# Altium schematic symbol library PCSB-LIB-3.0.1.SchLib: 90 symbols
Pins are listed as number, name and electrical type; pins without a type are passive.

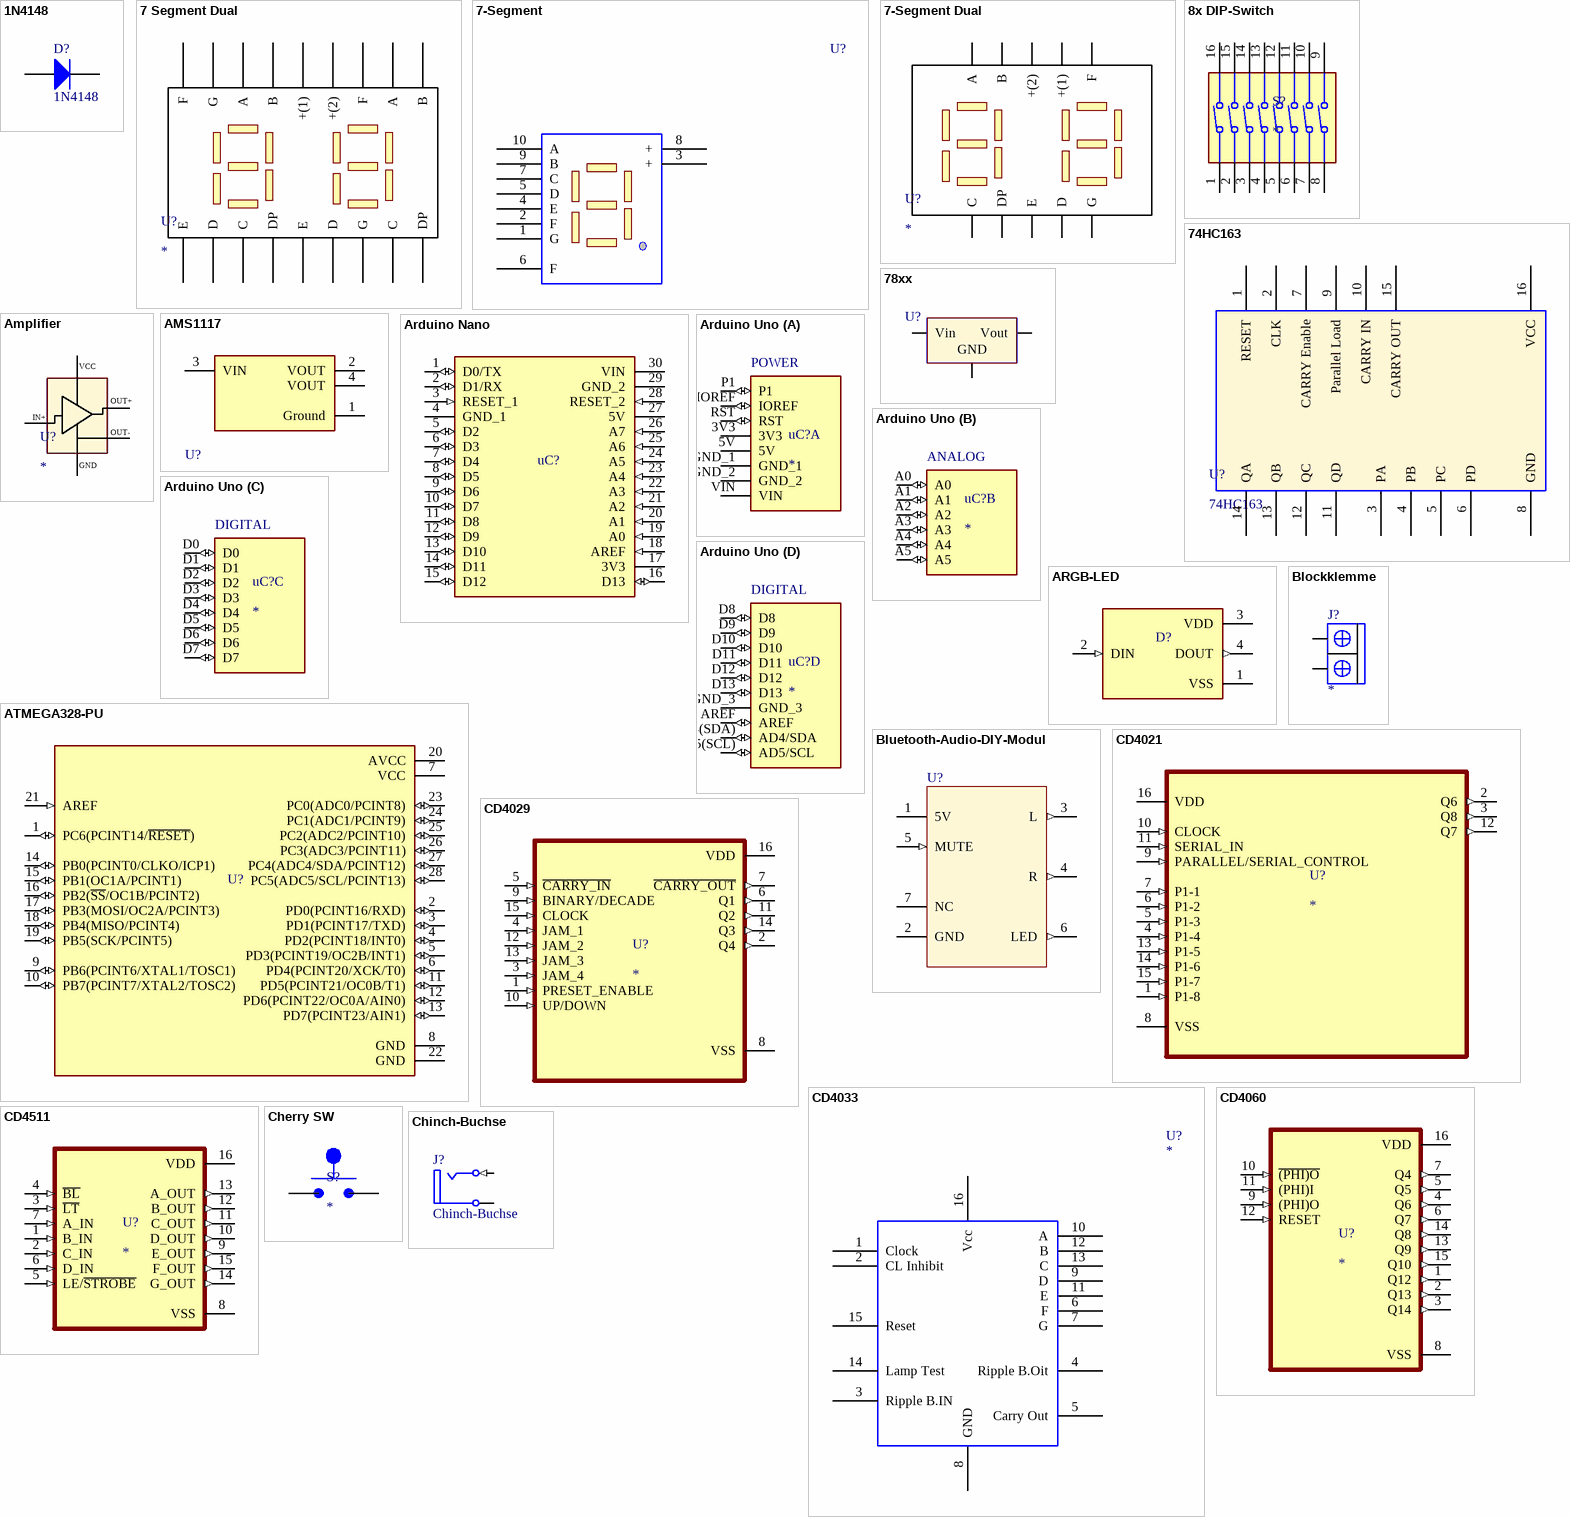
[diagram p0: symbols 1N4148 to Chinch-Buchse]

## 1N4148
designator D?
Diode
footprint DIODE-0.4
pins: 1 A, 2 K

## 7 Segment Dual
designator U?
footprint 7 Segment Dual Klein
footprint 7 Segment Dual Groß
pins: 1 E, 2 D, 3 C, 4 DP, 5 E, 6 D, 7 G, 8 C, 9 DP, 10 B, 11 A, 12 F, 13 +(2), 14 +(1), 15 B, 16 A, 17 G, 18 F

## 7-Segment
designator U?  (value not drawn)
7-Segment Display
footprint 7-Segment
pins: 1 G, 2 F, 3 +, 4 E, 5 D, 6 F, 7 C, 8 +, 9 B, 10 A

## 7-Segment Dual
designator U?
footprint 7 Seg Einfach
pins: 1 C, 2 DP, 3 E, 4 D, 5 G, 6 F, 7 +(1), 8 +(2), 9 B, 10 A

## 8x DIP-Switch
designator S?
MP: 418117170908; MF: WÃ¼rth Elektronik
footprint DIP 2x8
pins: 1, 2, 3, 4, 5, 6, 7, 8, 9, 10, 11, 12, 13, 14, 15, 16

## 74HC163
designator U?
Counter-IC; Mfr_Name: Texas Instruments
footprint DIP-16
pins: 1 RESET, 2 CLK, 3 PA, 4 PB, 5 PC, 6 PD, 7 CARRY Enable, 8 GND, 9 Parallel Load, 10 CARRY IN, 11 QD, 12 QC, 13 QB, 14 QA, 15 CARRY OUT, 16 VCC

## 78xx
designator U?  (value not drawn)
Spannungswander
footprint TO-92/BCE
footprint TO-220H
footprint TO-220V
pins: 1 Vin, 2 Vout, 3 GND

## Amplifier
designator U?
footprint Verstärker 5V
pins: 0, 1, 2, 3, 4

## AMS1117
designator U?
Spannungswandler; Manufacturer Part Number: AMS1117-3.3; Manufacturer: Advanced Monolithic Systems; Dropout Voltage: 1.1V; Output Type: Fixed; Nominal Supply Current: 5mA; Output Current: 1A; Output Voltage: 3.3V; Max Power Dissipation: 1.2W; Max Supply Voltage: 15V; Number Of Outputs: 1; Standoff Height: 0.64mm; Max Junction Temp: +125°C
footprint AMS1117_1
footprint AMS1117_2
footprint AMS1117_3
pins: 1 Ground (power), 2 VOUT, 3 VIN (power), 4 VOUT

## Arduino Nano
designator uC?  (value not drawn)
Microcontroller; MP: A000005
footprint Arduino-Nano
pins: 1 D0/TX (io), 2 D1/RX (io), 3 RESET_1 (in), 4 GND_1 (power), 5 D2 (io), 6 D3 (io), 7 D4 (io), 8 D5 (io), 9 D6 (io), 10 D7 (io), 11 D8 (io), 12 D9 (io), 13 D10 (io), 14 D11 (io), 15 D12 (io), 16 D13 (io), 17 3V3 (power), 18 AREF (in), 19 A0 (in), 20 A1 (in), 21 A2 (in), 22 A3 (in), 23 A4 (in), 24 A5 (in), 25 A6 (in), 26 A7 (in), 27 5V (power), 28 RESET_2 (in), 29 GND_2 (power), 30 VIN (power)

## Arduino Uno
designator uC?
MP: A000066; MF: Arduino
footprint Arduino Uno
part A pins: 3V3 (power), 5V (power), GND_1 (power), GND_2 (power), IOREF (io), P1 (io), RST (io), VIN (power)
part B pins: A0 (io), A1 (io), A2 (io), A3 (io), A4 (io), A5 (io)
part C pins: D0 (io), D1 (io), D2 (io), D3 (io), D4 (io), D5 (io), D6 (io), D7 (io)
part D pins: A4(SDA) AD4/SDA (io), A5(SCL) AD5/SCL (io), AREF (io), D8 (io), D9 (io), D10 (io), D11 (io), D12 (io), D13 (io), GND_3 (power)

## ARGB-LED
designator D?  (value not drawn)
Addressable LED; MP: 1655
footprint LED_ARGB
pins: 1 VSS (power), 2 DIN (in), 3 VDD (power), 4 DOUT (out)

## ATMEGA328-PU
designator U?  (value not drawn)
Microcontroller; MF: Microchip Technology; MP: ATMEGA328-PU
footprint atmega
pins: 1 PC6(PCINT14/~{RESET}) (io), 2 PD0(PCINT16/RXD) (io), 3 PD1(PCINT17/TXD) (io), 4 PD2(PCINT18/INT0) (io), 5 PD3(PCINT19/OC2B/INT1) (io), 6 PD4(PCINT20/XCK/T0) (io), 7 VCC (power), 8 GND (power), 9 PB6(PCINT6/XTAL1/TOSC1) (io), 10 PB7(PCINT7/XTAL2/TOSC2) (io), 11 PD5(PCINT21/OC0B/T1) (io), 12 PD6(PCINT22/OC0A/AIN0) (io), 13 PD7(PCINT23/AIN1) (io), 14 PB0(PCINT0/CLKO/ICP1) (io), 15 PB1(OC1A/PCINT1) (io), 16 PB2(~{SS}/OC1B/PCINT2) (io), 17 PB3(MOSI/OC2A/PCINT3) (io), 18 PB4(MISO/PCINT4) (io), 19 PB5(SCK/PCINT5) (io), 20 AVCC (power), 21 AREF (in), 22 GND (power), 23 PC0(ADC0/PCINT8) (io), 24 PC1(ADC1/PCINT9) (io), 25 PC2(ADC2/PCINT10) (io), 26 PC3(ADC3/PCINT11) (io), 27 PC4(ADC4/SDA/PCINT12) (io), 28 PC5(ADC5/SCL/PCINT13) (io)

## Blockklemme
designator J?
Stecker
footprint Blockklemme
pins: 1, 2

## Bluetooth-Audio-DIY-Modul
designator U?  (value not drawn)
Bluetooth Modul
footprint Bluetooth Audio SIP7
pins: 1 5V (power), 2 GND (power), 3 L (out), 4 R (out), 5 MUTE (in), 6 LED (out), 7 NC

## CD4021
designator U?
MF: Texas Instruments; MP: CD4021BEE4
footprint DIP-16
pins: 1 P1-8 (in), 2 Q6 (out), 3 Q8 (out), 4 P1-4 (in), 5 P1-3 (in), 6 P1-2 (in), 7 P1-1 (in), 8 VSS, 9 PARALLEL/SERIAL_CONTROL (in), 10 CLOCK (in), 11 SERIAL_IN (in), 12 Q7 (out), 13 P1-5 (in), 14 P1-6 (in), 15 P1-7 (in), 16 VDD (power)

## CD4029
designator U?
MP: CD4029BE; MF: Texas Instruments
footprint DIP-16
pins: 1 PRESET_ENABLE (in), 2 Q4 (out), 3 JAM_4 (in), 4 JAM_1 (in), 5 ~{CARRY_IN} (in), 6 Q1 (out), 7 ~{CARRY_OUT} (out), 8 VSS (power), 9 BINARY/DECADE (in), 10 UP/DOWN (in), 11 Q2 (out), 12 JAM_2 (in), 13 JAM_3 (in), 14 Q3 (out), 15 CLOCK (in), 16 VDD (power)

## CD4033
designator U?
IC
footprint DIP-16
footprint SO-16
pins: 1 Clock, 2 CL Inhibit, 3 Ripple B.IN, 4 Ripple B.Oit, 5 Carry Out, 6 F, 7 G, 8 GND, 9 D, 10 A, 11 E, 12 B, 13 C, 14 Lamp Test, 15 Reset, 16 Vcc

## CD4060
designator U?
MP: CD4060BE; MF: Texas Instruments
footprint DIP-16
pins: 1 Q12 (out), 2 Q13 (out), 3 Q14 (out), 4 Q6 (out), 5 Q5 (out), 6 Q7 (out), 7 Q4 (out), 8 VSS (power), 9 (PHI)O (in), 10 ~{(PHI)O} (in), 11 (PHI)I (in), 12 RESET (in), 13 Q9 (out), 14 Q8 (out), 15 Q10 (out), 16 VDD (power)

## CD4511
designator U?
MP: CD4511BE
footprint DIP-16
pins: 1 B_IN (in), 2 C_IN (in), 3 ~{LT} (in), 4 ~{BL} (in), 5 LE/~{STROBE} (in), 6 D_IN (in), 7 A_IN (in), 8 VSS (power), 9 E_OUT (out), 10 D_OUT (out), 11 C_OUT (out), 12 B_OUT (out), 13 A_OUT (out), 14 G_OUT (out), 15 F_OUT (out), 16 VDD (power)

## Cherry SW
designator S?
Switch Key N.O. SPST 0.01A 12VAC 12VDC 0.5N PC Pins 20000000Cycles Thru-Hole; MP: COM-13834
footprint Cherry MX
pins: 1, 2

## Chinch-Buchse
designator J?
PackageDocument: 2003; PCB_Layout: Complies with manufacturer's recommendation.; DrillAndSlotSize: Corresponds to nominal value.; Lieferant: RS; Bestellnummer: 909-2235; Preis /Stk: 0,790
footprint CHINCH (RCA-Buchse bestellbar bei RS  Nr. 913-1021)
pins: 1 T (in) "Tip", 5 S (power) "Sleeve (Ground)"

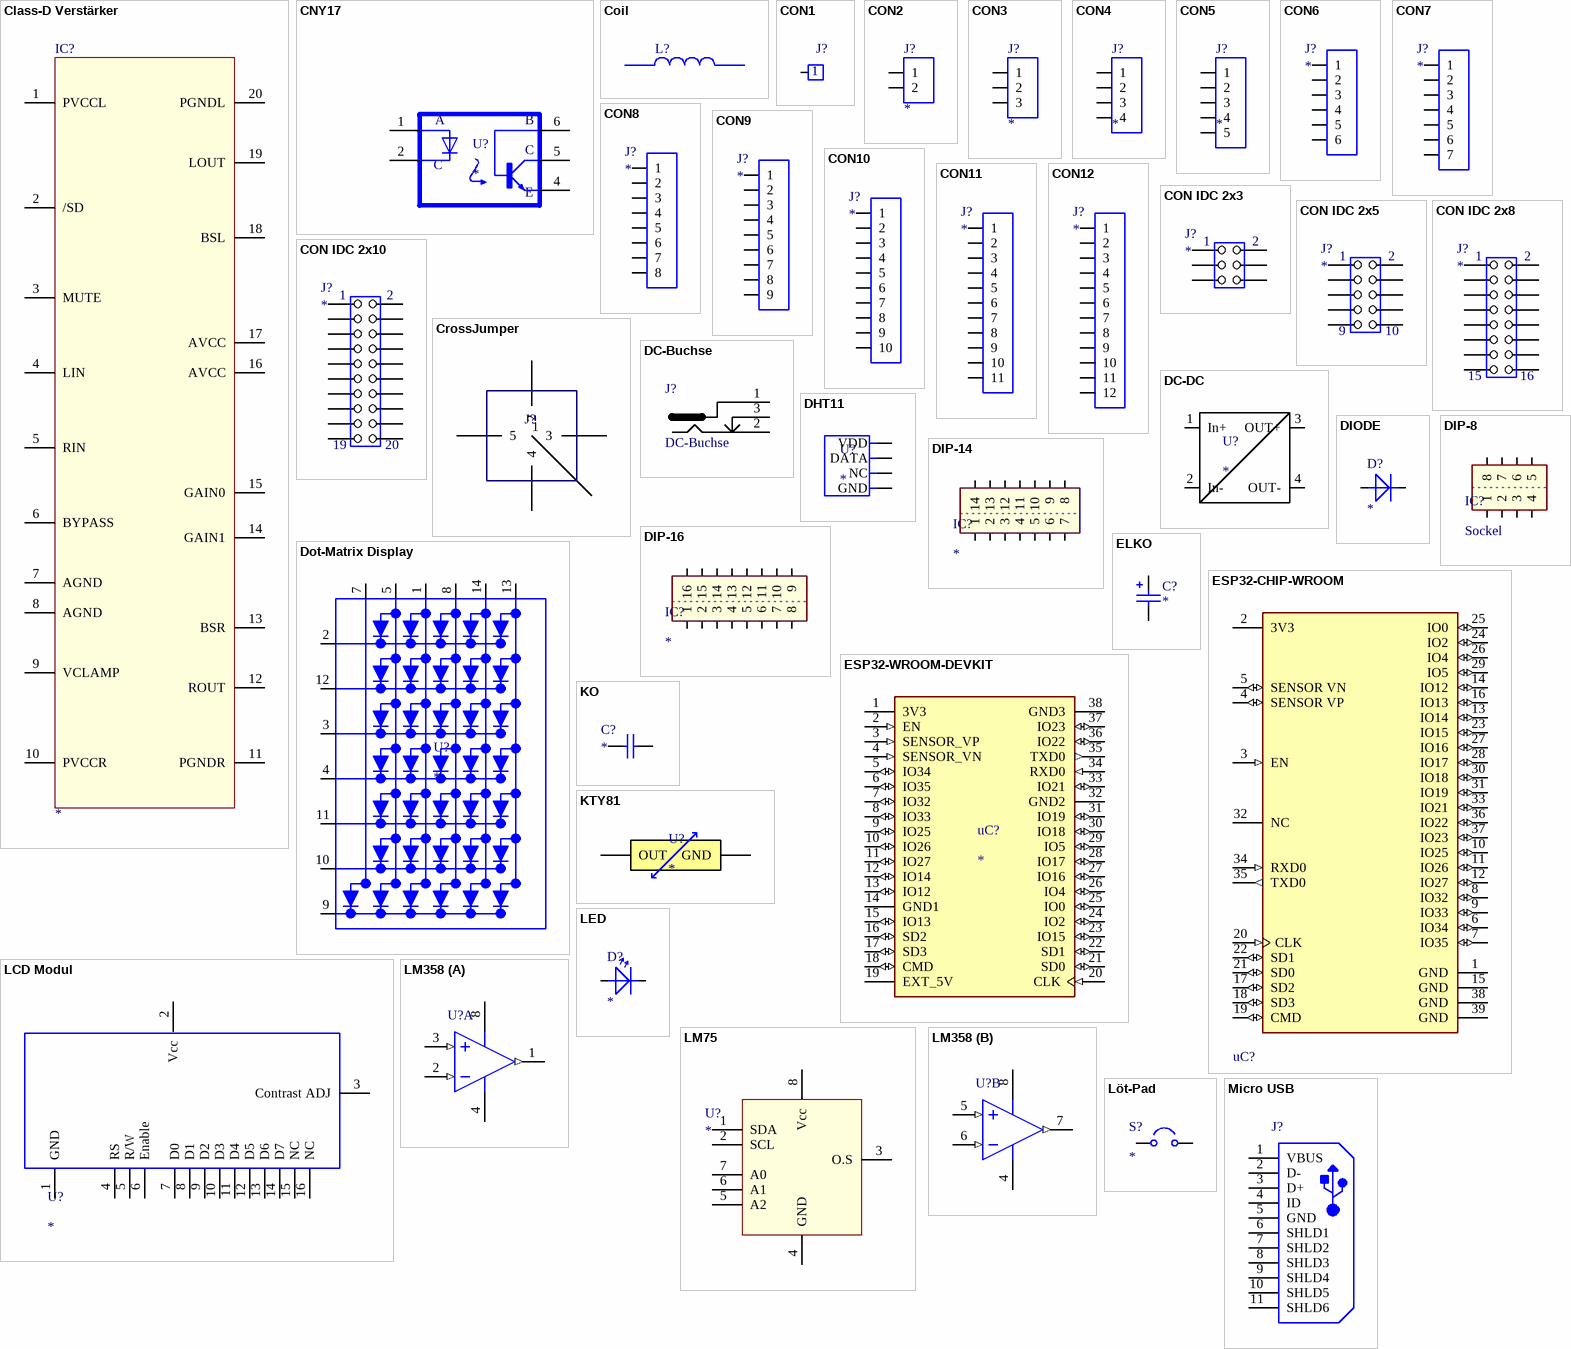
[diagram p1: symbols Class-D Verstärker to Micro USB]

## Class-D Verstärker
designator IC?
Class-D; Value: TPA3125; Lieferant: RS; Bestellnummer: 121-9381; Preis /Stk: 1,977
footprint DIP-20
pins: 1 PVCCL, 2 /SD, 3 MUTE, 4 LIN, 5 RIN, 6 BYPASS, 7 AGND, 8 AGND, 9 VCLAMP, 10 PVCCR, 11 PGNDR, 12 ROUT, 13 BSR, 14 GAIN1, 15 GAIN0, 16 AVCC, 17 AVCC, 18 BSL, 19 LOUT, 20 PGNDL

## CNY17
designator U?
Optoisolator Transistor Output 5000Vrms 1 Channel 6-DIP; MP: CNY17F-3; MF: Vishay Semiconductor
footprint DIP-6
pins: 1 A, 2 C, 4 E, 5 C`, 6

## Coil
designator L?, comment 80Ohm@100MHz  (value not drawn)
Spule; Lieferant: Pollin; Bestellnummer: 888-3033; Preis /Stk: 0,051
footprint Axial-0.4
footprint Coil - 5.08 x 8
footprint 1808C (Chip Capacitor, 2-Leads, Body 4,5x2,0mm, IPC Medium Density)
pins: 1, 2

## CON1
designator J?  (value not drawn)
Stecker
footprint Pin1
pins: 1

## CON2
designator J?
Stecker
footprint KL-2
footprint SIP-2
pins: 1, 2

## CON3
designator J?
Stecker
footprint Sip-3
footprint KL-3
pins: 1, 2, 3

## CON4
designator J?
Stecker
footprint USB_TYPB
footprint Sip-4
pins: 1, 2, 3, 4

## CON5
designator J?
Stecker
footprint SIP-5
pins: 1, 2, 3, 4, 5

## CON6
designator J?
Stecker
footprint SIP-6
pins: 1, 2, 3, 4, 5, 6

## CON7
designator J?
Stecker
footprint SIP-7
pins: 1, 2, 3, 4, 5, 6, 7

## CON8
designator J?
Stecker
footprint SIP-8
pins: 1, 2, 3, 4, 5, 6, 7, 8

## CON9
designator J?
Stecker
footprint SIP-9
footprint DB9SL
pins: 1, 2, 3, 4, 5, 6, 7, 8, 9

## CON10
designator J?
Stecker
footprint SIP-10
pins: 1, 2, 3, 4, 5, 6, 7, 8, 9, 10

## CON11
designator J?
Stecker
footprint SIP-11
pins: 1, 2, 3, 4, 5, 6, 7, 8, 9, 10, 11

## CON12
designator J?
Stecker
footprint SIP-12
pins: 1, 2, 3, 4, 5, 6, 7, 8, 9, 10, 11, 12

## CON IDC 2x3
designator J?
Stecker
footprint PFOSTEN_2x3
pins: 1, 2, 3, 4, 5, 6

## CON IDC 2x5
designator J?
Stecker
footprint PFOSTEN_2x5H
footprint PFOSTEN_2x5V
pins: 1, 2, 3, 4, 5, 6, 7, 8, 9, 10

## CON IDC 2x8
designator J?
Stecker
footprint PFOSTEN_2x8
pins: 1, 2, 3, 4, 5, 6, 7, 8, 9, 10, 11, 12, 13, 14, 15, 16

## CON IDC 2x10
designator J?
Stecker
footprint PFOSTEN_2x10
pins: 1, 2, 3, 4, 5, 6, 7, 8, 9, 10, 11, 12, 13, 14, 15, 16, 17, 18, 19, 20

## CrossJumper
designator J?  (value not drawn)
footprint CrossJumper
pins: 1, 2, 3, 4, 5

## DC-Buchse
designator J?
Lieferant: RS; Bestellnummer: 448-382; Preis /Stk: 0,267
footprint CJ-25 (DC-Buchse 2.1mm Bestellbar bei RS Nr. 448-382)
pins: 1, 2, 3

## DC-DC
designator U?
DC-DC Wandler
footprint dcdc
pins: 1 In+, 2 In-, 3 OUT+, 4 OUT-

## DHT11
designator U?
Temparatur Sensor; MP: DHT11; MF: Panasonic Industrial Automation Sales
footprint SNR4-2.54-15.5X12.0X5.5MM
pins: 1 VDD (power), 2 DATA (power), 3 NC, 4 GND (power)

## DIODE
designator D?
Diode
footprint Diode-0.4
footprint Diode-0.5
footprint DIODE-0.6
pins: 1 A, 2 K

## DIP-8
designator IC?, comment Sockel
footprint DIP-8
pins: 1, 2, 3, 4, 5, 6, 7, 8

## DIP-14
designator IC?
footprint DIP-14
pins: 1, 2, 3, 4, 5, 6, 7, 8, 9, 10, 11, 12, 13, 14

## DIP-16
designator IC?
footprint DIP-16
pins: 1, 2, 3, 4, 5, 6, 7, 8, 9, 10, 11, 12, 13, 14, 15, 16

## Dot-Matrix Display
designator U?
Dot Matrix Display Module 5 x 7 Common Cathode Row, Common Anode Column Green 2.1V 0.39 L x 0.73 W x 0.14 H (9.80mm x 18.50mm x 3.50mm); MF: Lite-On Inc.; MP: LTP-305G
footprint DOTMatrixDisplay
pins: 1 ANODE_COLUMN_2, 2 CATHODE_ROW_1, 3 CATHODE_ROW_3, 4 CATHODE_ROW_4, 5 ANODE_COLUMN_1, 7 ANODE_DECIMAL_POINT, 8 ANODE_COLUMN_3, 9 CATHODE_ROW_7, 10 CATHODE_ROW_6, 11 CATHODE_ROW_5, 12 CATHODE_ROW_2, 13 ANODE_COLUMN_5, 14 ANODE_COLUMN_4

## ELKO
designator C?
Elko
footprint RB-.1/.2
footprint RB-.1/.3
footprint RB-.2/.4
footprint RB-.3/.6
pins: 1, 2

## ESP32-CHIP-WROOM
designator uC?
Microcontroller; Manufacturer: Espressif Systems; Manufacturer Part Number: ESP32-WROOM-32D; Max Supply Voltage: 3.6V; Nominal Supply Current: 500mA; Max Frequency: 2484MHz; Number Of Adc Channels: 16; Number Of Gpio: 32; Interface: I2C,SPI,UART,Ethernet,I2S,Other; Data Rate: 150Mbits/s; Min Supply Voltage: 3V; Bandwidth: 72MHz; Sensitivity: -98dBm
footprint ESP32-DEV
pins: 1 GND (power), 2 3V3 (power), 3 EN (in), 4 SENSOR VP (io), 5 SENSOR VN (io), 6 IO34 (io), 7 IO35 (io), 8 IO32 (io), 9 IO33 (io), 10 IO25 (io), 11 IO26 (io), 12 IO27 (io), 13 IO14 (io), 14 IO12 (io), 15 GND (power), 16 IO13 (io), 17 SD2 (io), 18 SD3 (io), 19 CMD (io), 20 CLK (in), 21 SD0 (io), 22 SD1 (io), 23 IO15 (io), 24 IO2 (io), 25 IO0 (io), 26 IO4 (io), 27 IO16 (io), 28 IO17 (io), 29 IO5 (io), 30 IO18 (io), 31 IO19 (io), 32 NC, 33 IO21 (io), 34 RXD0 (in), 35 TXD0 (out), 36 IO22 (io), 37 IO23 (io), 38 GND (power), 39 GND (power)

## ESP32-WROOM-DEVKIT
designator uC?
MP: ESP32-DEVKITC; MF: Espressif Systems
footprint ESP32-WROOM
pins: 1 3V3 (power), 2 EN (in), 3 SENSOR_VP (in), 4 SENSOR_VN (in), 5 IO34 (io), 6 IO35 (io), 7 IO32 (io), 8 IO33 (io), 9 IO25 (io), 10 IO26 (io), 11 IO27 (io), 12 IO14 (io), 13 IO12 (io), 14 GND1 (power), 15 IO13 (io), 16 SD2 (io), 17 SD3 (io), 18 CMD (io), 19 EXT_5V (power), 20 CLK (in), 21 SD0 (io), 22 SD1 (io), 23 IO15 (io), 24 IO2 (io), 25 IO0 (io), 26 IO4 (io), 27 IO16 (io), 28 IO17 (io), 29 IO5 (io), 30 IO18 (io), 31 IO19 (io), 32 GND2 (power), 33 IO21 (io), 34 RXD0 (in), 35 TXD0 (out), 36 IO22 (io), 37 IO23 (io), 38 GND3 (power)

## KO
designator C?
Kondensator
footprint rad-7.2/2.5/5
footprint RAD-7.2/3.5/5
footprint 0603
footprint 0805
footprint 1206
footprint KO-600mil
pins: 1, 2

## KTY81
designator U?
PTC Thermistor 2 kOhms TO-226-2, TO-92-2 (TO-226AC); MP: KTY81; MF: NXP USA
footprint TO-92/2
pins: 1 OUT, 2 GND

## LCD Modul
designator U?
LCD
footprint WM-C1610M
pins: 1 GND, 2 Vcc, 3 Contrast ADJ, 4 RS, 5 R/W, 6 Enable, 7 D0, 8 D1, 9 D2, 10 D3, 11 D4, 12 D5, 13 D6, 14 D7, 15 NC, 16 NC

## LED
designator D?
Diode
footprint LED-5
footprint LED-3
pins: 1 A, 2 K

## LM75
designator U?
IC
footprint SO-8
pins: 1 SDA, 2 SCL, 3 O.S, 4 GND, 5 A2, 6 A1, 7 A0, 8 Vcc

## LM358
designator U?
Operationsverstärker; PartNumber: LM358AN; Manufacturer: National Semiconductor; PackageTopMarking: NSUZXYTTE#*LM*358AN; PowerWise: N; CompType: Amplifiers
footprint DIP-8
footprint SO-8
pins on every part: 4 GND (power), 8 V+ (power)
part A pins: 1 OUTA (out), 2 INA- (in), 3 INA+ (in)
part B pins: 5 INB+ (in), 6 INB- (in), 7 OUTB (out)

## Löt-Pad
designator S?
footprint SMD-Brigde NC
footprint SMD-Brigde NO
pins: 1 0, 2 1

## Micro USB
designator J?
Number of Ports: 1Port; Current Rating: 1.8A; Brand: Molex; Mounting Angle: Right; Gender: Female; Connector Type: MicroUSBTypeABreceptacle; Number of Contacts: 5Contact; Voltage Rating: 30VAC
footprint Micro-USB (USB, MICRO B, Body 7.491x4.695 mm, Pitch 0.65 mm)
pins: 1 VBUS, 2 D-, 3 D+, 4 ID, 5 GND, 6 SHLD1, 7 SHLD2, 8 SHLD3, 9 SHLD4, 10 SHLD5, 11 SHLD6

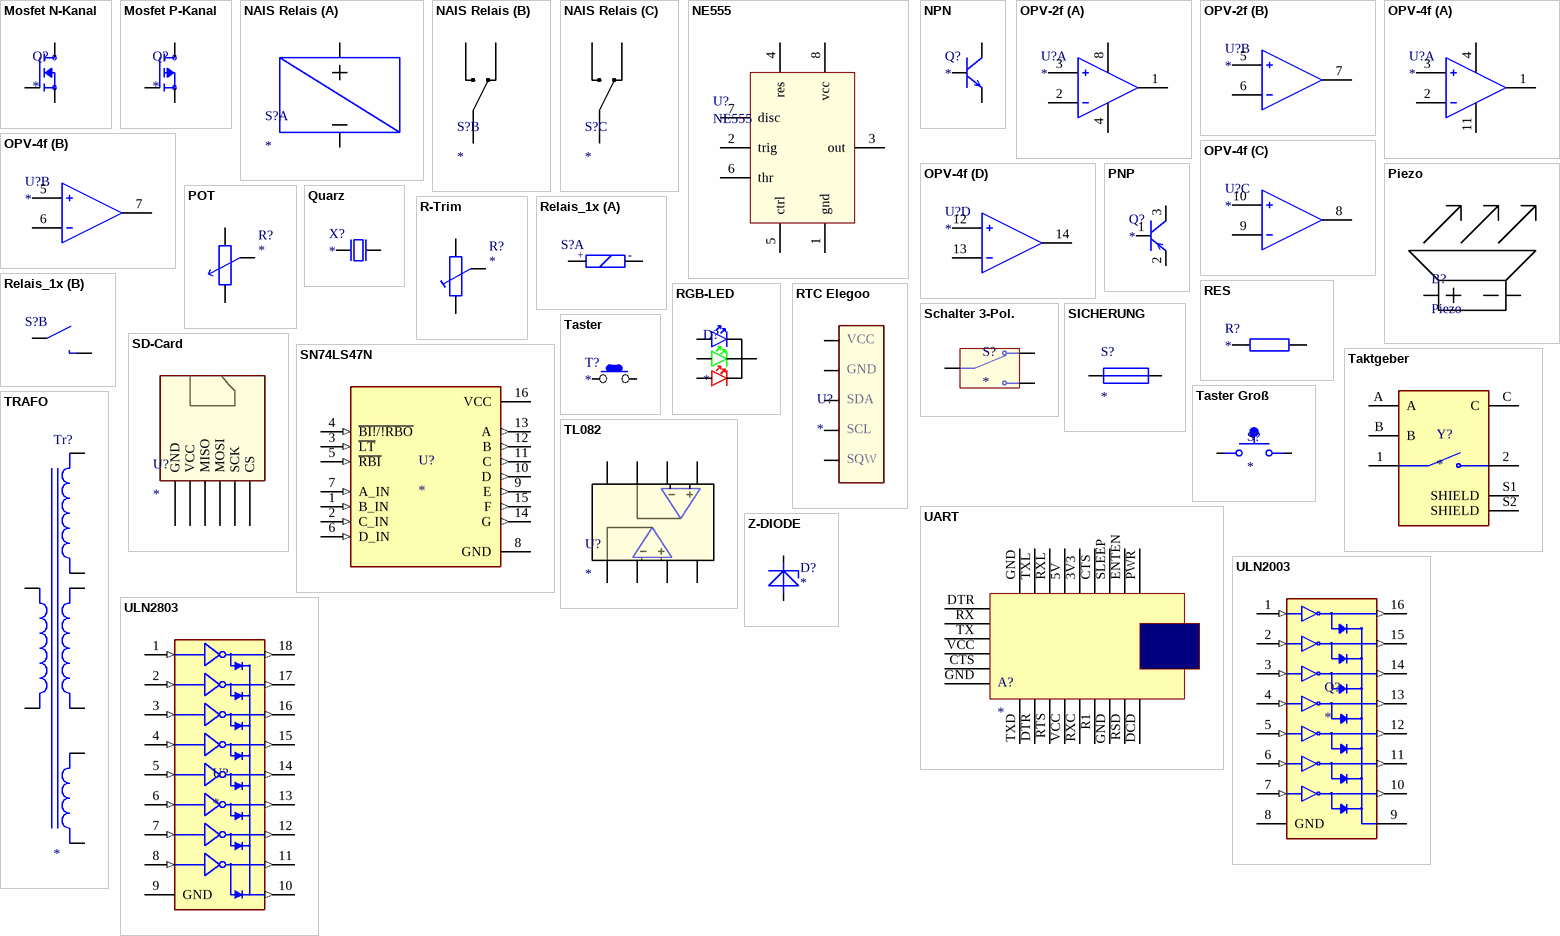
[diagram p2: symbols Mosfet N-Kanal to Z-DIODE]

## Mosfet N-Kanal
designator Q?
FET; MP: IRFZ44NPBF; MF: Infineon
footprint MOSFET
pins: 1 G, 2 D, 3 S

## Mosfet P-Kanal
designator Q?
FET; MP: IRFZ44NPBF; MF: Infineon
footprint MOSFET
pins: 1 G, 2 D, 3 S

## NAIS Relais
designator S?
footprint NAIS-Relais
part A pins: 4, 5
part B pins: 1, 2, 3
part C pins: 6, 7, 8

## NE555
designator U?
Timer
footprint DIP-8
footprint SO-8
pins: 1 gnd, 2 trig, 3 out, 4 res, 5 ctrl, 6 thr, 7 disc, 8 vcc

## NPN
designator Q?
Transistor
footprint TO-92/EBC
footprint TO-220V
footprint TO-220H
pins: 1 B, 2 E, 3 C

## OPV-2f
designator U?
IC
footprint DIP-8
part A pins: 1 out, 2 I, 3 NI, 4 Vee, 8 Vcc
part B pins: 5 NI, 6 I, 7 out

## OPV-4f
designator U?
IC
footprint DIP-14
part A pins: 1 out, 2 I, 3 NI, 4 Vcc, 11 Vee
part B pins: 5 NI, 6 I, 7 out
part C pins: 8 out, 9 I, 10 NI
part D pins: 12 NI, 13 I, 14 out

## Piezo
designator B?
footprint Piezo
pins: 1, 2

## PNP
designator Q?
Transistor
footprint TO-92/EBC
footprint TO-220V
footprint TO-220H
pins: 1 B, 2 E, 3 C

## POT
designator R?
Potentiometer; Set Position: 0.5
footprint PT15
footprint TP-.2/.4
footprint ALPS_V
pins: 1, 2, 3

## Quarz
designator X?
Quarz
footprint Quarz
pins: 1, 2

## R-Trim
designator R?
Potentiometer
footprint TP-.2/.4
pins: 1, 2, 3

## Relais_1x
designator S?
Relais
footprint Relais (K?)
part A pins: 1 +, 2 -
part B pins: 3, 4

## RES
designator R?
Widerstand
footprint Axial-0.4
footprint Axial-0.7
footprint 0603
footprint 0805
footprint 1206
simulation model Model Name (Model Description)
pins: 1, 2

## RGB-LED
designator D?
Diode
footprint RGBLED
pins: 1, 2, 3, 4

## RTC Elegoo
designator U?
footprint Elegoo RTC
pins: 1, 2, 3, 4, 5

## Schalter 3-Pol.
designator S?
Toggle Switch; MP: 100SP1T1B4M2QE
footprint SW_100SP1T1B4M2QE
pins: 1, 2, 3

## SD-Card
designator U?
footprint SD-Card - H
footprint SD-Card - V
pins: 0 GND, 1 VCC, 2 MISO, 3 MOSI, 4 SCK, 5 CS

## SICHERUNG
designator S?
Sicherung; Text Field1: Strom
footprint SICHERUNG
pins: 1, 2

## SN74LS47N
designator U?
BCD-to-Seven-Segment Decoders/Drivers 16-PDIP 0 to 70; MP: SN74LS47N; MF: Texas Instruments
footprint DIP-16
pins: 1 B_IN (in), 2 C_IN (in), 3 ~{LT} (in), 4 ~{BI!/!RBO} (in), 5 ~{RBI} (in), 6 D_IN (in), 7 A_IN (in), 8 GND (power), 9 E (out), 10 D (out), 11 C (out), 12 B (out), 13 A (out), 14 G (out), 15 F (out), 16 VCC (power)

## Taktgeber
designator Y?
Rotary Encoder; MP: 482016514001; MF: WÃ¼rth Elektronik
footprint Rotary
pins: 1, 2, A, B, C, S1 SHIELD, S2 SHIELD

## Taster
designator T?
Taster
footprint Tast
footprint Taster 20mm
pins: 1, 2

## Taster Groß
designator S?
Taster Groß; MP: TL1100EF160Q
footprint SW_TL1100EF160Q
pins: 1, 2

## TL082
designator U?
OPV
footprint DIP-8
pins: 1, 2, 3, 4, 5, 6, 7, 8

## TRAFO
designator Tr?
Trafo; Text Field1: Sec1; Text Field2: Sec2; Text Field3: Sec3
footprint EI66
pins: 2 230V, 7 230V, 9 16V, 10 16V, 12 16V, 13 16V, 15 8V, 16 8V

## UART
designator A?
footprint uart
pins: 3V3 13, 5V 12, CTS 14, CTS 19, DCD 8, DTR 1, DTR 23, ENTEN 16, GND 6, GND 9, GND 18, PWR 17, R1 5, RSD 7, RTS 2, RX 22, RXC 4, RXL 11, SLEEP 15, TX 21, TXD 0, TXL 10, VCC 3, VCC 20

## ULN2003
designator Q?
Darlingtor-Transistor; MP: ULN2003AN
footprint DIP-16
pins: 1 1B (in), 2 2B (in), 3 3B (in), 4 4B (in), 5 5B (in), 6 6B (in), 7 7B (in), 8 GND (power), 9 COM, 10 7C (out), 11 6C (out), 12 5C (out), 13 4C (out), 14 3C (out), 15 2C (out), 16 1C (out)

## ULN2803
designator U?
Darlington-Transistor; MP: ULN2803A; MF: STMicroelectronics
footprint DIP-18
pins: 1 IN_1 (in), 2 IN_2 (in), 3 IN_3 (in), 4 IN_4 (in), 5 IN_5 (in), 6 IN_6 (in), 7 IN_7 (in), 8 IN_8 (in), 9 GND (power), 10 COMMON (out), 11 OUT_8 (out), 12 OUT_7 (out), 13 OUT_6 (out), 14 OUT_5 (out), 15 OUT_4 (out), 16 OUT_3 (out), 17 OUT_2 (out), 18 OUT_1 (out)

## Z-DIODE
designator D?
Z-Diode
footprint DIODE-0.4
footprint SOD-80
pins: 1 A, 2 K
